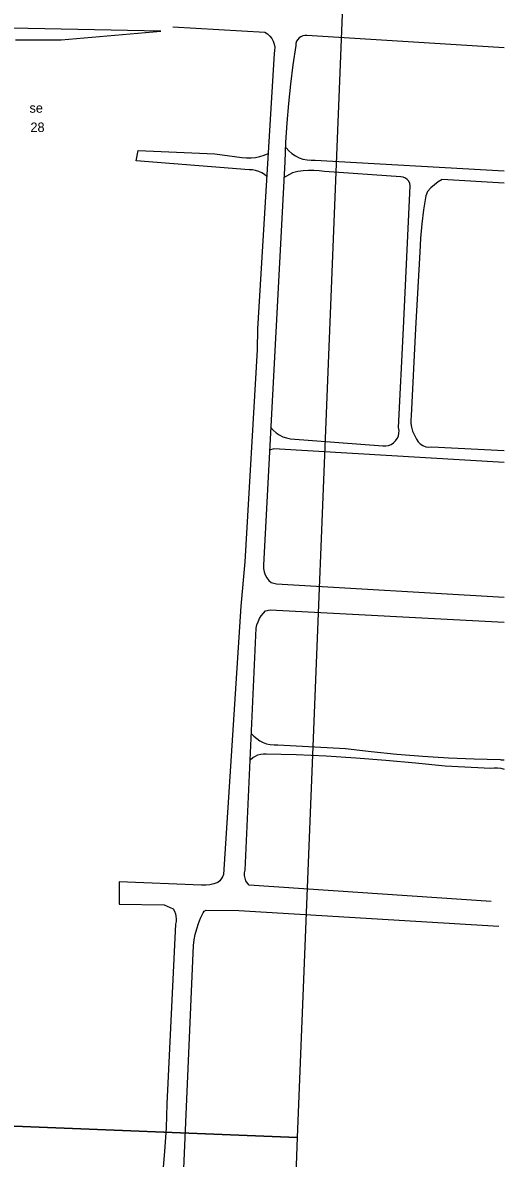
# Model space of a CAD drawing. Extents: x -9648 to 41057, y -12373 to 40276.
# Drawn here: x 9040 to 9546, y 10895 to 12090 of the extents above; entities that cross this region are included whole.
import ezdxf

# ---------------------------------------------------------------- set-up
doc = ezdxf.new("R2010")
doc.units = 0
doc.layers.add('SC_Scratch1', color=7, linetype='Continuous')
doc.layers.add('SH_Data', color=7, linetype='Continuous')

msp = doc.modelspace()

# ---------------------------------------------------------------- linework, layer by layer
at = {"layer": 'SC_Scratch1'}
for p, q in [((9419, 13174.6), (9328.4, 10916.5)), ((9328.4, 10916.5), (7789.6, 10978.2)), ((7789.6, 10978.2), (9328.4, 10916.5)), ((9328.4, 10916.5), (9237.7, 8658.3))]:
    msp.add_line(p, q, dxfattribs=at)
at = {"layer": 'SH_Data'}
for p, q in [((9184.9, 12081), (9027.9, 12084.4)), ((9197.4, 12085.7), (9294.3, 12080)), ((9079.9, 12071.9), (9184.9, 12081)), ((9294.3, 12080), (9297.1, 12078.3)), ((9297.1, 12078.3), (9299.5, 12076)), ((9299.5, 12076), (9301.6, 12073.5)), ((9301.6, 12073.5), (9303.1, 12070.6)), ((9328.9, 12072.4), (9327.8, 12070.5)), ((9330.4, 12074), (9328.9, 12072.4)), ((9332.2, 12075.3), (9330.4, 12074)), ((9334.2, 12076.2), (9332.2, 12075.3)), ((9336.4, 12076.7), (9334.2, 12076.2)), ((9338.6, 12076.6), (9336.4, 12076.7)), ((9546.3, 12063.7), (9338.6, 12076.6)), ((9032.1, 12071.9), (9079.9, 12071.9)), ((9303.1, 12070.6), (9304.2, 12067.4)), ((9304.6, 12060.9), (9304, 12057.7)), ((9304.2, 12067.4), (9304.7, 12064.2)), ((9304.7, 12064.2), (9304.6, 12060.9)), ((9326.9, 12066.1), (9323.9, 12045.8)), ((9327.1, 12068.3), (9326.9, 12066.1)), ((9327.8, 12070.5), (9327.1, 12068.3)), ((9304, 12057.7), (9286.5, 11767.9)), ((9323.9, 12045.8), (9321.3, 12025.4)), ((9321.3, 12025.4), (9319.2, 12005)), ((9319.2, 12005), (9317.4, 11984.5)), ((9317.4, 11984.5), (9316.1, 11964)), ((9158.8, 11944.5), (9161, 11955.4)), ((9161, 11955.4), (9241.8, 11951.9)), ((9316.1, 11964), (9315.2, 11943.5)), ((9316.7, 11958.4), (9319.6, 11955.2)), ((9319.6, 11955.2), (9322.9, 11952.4)), ((9277.8, 11935.1), (9158.8, 11944.5)), ((9241.8, 11951.9), (9270.1, 11948.3)), ((9270.1, 11948.3), (9275.2, 11947.7)), ((9275.2, 11947.7), (9279.9, 11947.7)), ((9279.9, 11947.7), (9284.6, 11948.1)), ((9284.6, 11948.1), (9289.2, 11949.1)), ((9289.2, 11949.1), (9293.7, 11950.6)), ((9315.2, 11943.5), (9293.1, 11519)), ((9293.7, 11950.6), (9298, 11952.5)), ((9322.9, 11952.4), (9326.5, 11950)), ((9326.5, 11950), (9330.4, 11948)), ((9330.4, 11948), (9334.4, 11946.6)), ((9334.4, 11946.6), (9338.7, 11945.6)), ((9338.7, 11945.6), (9343, 11945.2)), ((9343, 11945.2), (9347.3, 11945.4)), ((9347.3, 11945.4), (9546.3, 11934)), ((9281.3, 11935.1), (9277.8, 11935.1)), ((9284.6, 11934.6), (9281.3, 11935.1)), ((9287.9, 11933.6), (9284.6, 11934.6)), ((9291, 11932.2), (9287.9, 11933.6)), ((9293.9, 11930.4), (9291, 11932.2)), ((9296.5, 11928.3), (9293.9, 11930.4)), ((9323.4, 11932.2), (9313.9, 11926.9)), ((9328.9, 11933.3), (9323.4, 11932.2)), ((9334.5, 11934.1), (9328.9, 11933.3)), ((9340.2, 11934.4), (9334.5, 11934.1)), ((9345.8, 11934.4), (9340.2, 11934.4)), ((9351.5, 11934.1), (9345.8, 11934.4)), ((9357.1, 11933.3), (9351.5, 11934.1)), ((9437.4, 11927.9), (9357.1, 11933.3)), ((9439.9, 11927.6), (9437.4, 11927.9)), ((9442.2, 11926.6), (9439.9, 11927.6)), ((9440.4, 11768.5), (9447.3, 11918.4)), ((9444.2, 11925.1), (9442.2, 11926.6)), ((9445.8, 11923.1), (9444.2, 11925.1)), ((9446.9, 11920.9), (9445.8, 11923.1)), ((9447.3, 11918.4), (9446.9, 11920.9)), ((9472.7, 11919.4), (9468.9, 11916.1)), ((9476.7, 11922.4), (9472.7, 11919.4)), ((9481, 11925.1), (9476.7, 11922.4)), ((9546.3, 11921.2), (9481, 11925.1)), ((9463.8, 11907.8), (9461.3, 11893.1)), ((9465.4, 11912.5), (9463.8, 11907.8)), ((9468.9, 11916.1), (9465.4, 11912.5)), ((9461.3, 11893.1), (9459.4, 11878.3)), ((9459.4, 11878.3), (9458.2, 11863.4)), ((9458.2, 11863.4), (9457.5, 11848.4)), ((9457.5, 11848.4), (9452.8, 11768.3)), ((9286.5, 11767.9), (9286.3, 11745.7)), ((9434.9, 11663.9), (9440.4, 11768.5)), ((9452.8, 11768.3), (9448.4, 11676.1)), ((9286.3, 11745.7), (9273.4, 11522.6)), ((9448.4, 11676.1), (9448, 11672.1)), ((9448, 11672.1), (9448.1, 11668.1)), ((9448.1, 11668.1), (9448.7, 11664.2)), ((9300.3, 11664.3), (9303, 11661.1)), ((9303, 11661.1), (9306.1, 11658.4)), ((9306.1, 11658.4), (9309.5, 11656.1)), ((9309.5, 11656.1), (9313.2, 11654.2)), ((9313.2, 11654.2), (9317.1, 11653)), ((9433.6, 11652.3), (9434.8, 11655)), ((9434.8, 11655), (9435.4, 11658)), ((9435.5, 11661), (9434.9, 11663.9)), ((9435.4, 11658), (9435.5, 11661)), ((9448.7, 11664.2), (9449.8, 11660.3)), ((9449.8, 11660.3), (9451.3, 11656.6)), ((9451.3, 11656.6), (9453.3, 11653.1)), ((9317.1, 11653), (9321.2, 11652.2)), ((9321.2, 11652.2), (9418.5, 11644.6)), ((9418.5, 11644.6), (9421.5, 11644.6)), ((9421.5, 11644.6), (9424.4, 11645.1)), ((9424.4, 11645.1), (9427.2, 11646.2)), ((9427.2, 11646.2), (9429.7, 11647.8)), ((9429.7, 11647.8), (9431.9, 11649.8)), ((9431.9, 11649.8), (9433.6, 11652.3)), ((9453.3, 11653.1), (9453.9, 11651.7)), ((9453.9, 11651.7), (9455.6, 11649)), ((9455.6, 11649), (9457.9, 11646.7)), ((9457.9, 11646.7), (9460.6, 11645)), ((9460.6, 11645), (9463.6, 11643.8)), ((9463.6, 11643.8), (9466.7, 11643.3)), ((9466.7, 11643.3), (9469.9, 11643.5)), ((9469.9, 11643.5), (9546.3, 11639.8)), ((9303.9, 11641.6), (9299.1, 11640.1)), ((9546.3, 11627.3), (9303.9, 11641.6)), ((9273.4, 11522.6), (9269, 11476)), ((9293.1, 11519), (9293.1, 11515.6)), ((9293.1, 11515.6), (9293.6, 11512.1)), ((9293.6, 11512.1), (9294.7, 11508.8)), ((9294.7, 11508.8), (9296.4, 11505.8)), ((9296.4, 11505.8), (9298.5, 11503)), ((9298.5, 11503), (9301.1, 11500.7)), ((9301.1, 11500.7), (9306.6, 11499.4)), ((9306.6, 11499.4), (9546.3, 11485.5)), ((9269, 11476), (9250.9, 11193.6)), ((9287.2, 11459.6), (9288.7, 11462.8)), ((9288.7, 11462.8), (9290.6, 11465.8)), ((9290.6, 11465.8), (9292.8, 11468.6)), ((9292.8, 11468.6), (9295.2, 11471.1)), ((9295.2, 11471.1), (9300, 11472.1)), ((9300, 11472.1), (9546.3, 11459)), ((9273.6, 11198.2), (9285.2, 11452.7)), ((9285.2, 11452.7), (9286, 11456.2)), ((9286, 11456.2), (9287.2, 11459.6)), ((9280.1, 11341.9), (9282.8, 11339)), ((9282.8, 11339), (9285.8, 11336.5)), ((9285.8, 11336.5), (9289.1, 11334.3)), ((9289.1, 11334.3), (9292.6, 11332.5)), ((9292.6, 11332.5), (9296.2, 11331.2)), ((9296.2, 11331.2), (9300.1, 11330.3)), ((9284.4, 11318.2), (9287.1, 11319.4)), ((9287.1, 11319.4), (9290, 11320.2)), ((9290, 11320.2), (9292.9, 11320.6)), ((9292.9, 11320.6), (9295.9, 11320.6)), ((9295.9, 11320.6), (9327.4, 11319.7)), ((9300.1, 11330.3), (9304, 11329.9)), ((9304, 11329.9), (9307.9, 11329.9)), ((9307.9, 11329.9), (9379.3, 11326.2)), ((9327.4, 11319.7), (9358.8, 11318.3)), ((9379.3, 11326.2), (9406.3, 11323)), ((9406.3, 11323), (9433.3, 11320.3)), ((9433.3, 11320.3), (9460.4, 11318.1)), ((9278.9, 11314.1), (9281.8, 11316.6)), ((9281.8, 11316.6), (9284.4, 11318.2)), ((9358.8, 11318.3), (9390.2, 11316.3)), ((9390.2, 11316.3), (9421.6, 11314)), ((9421.6, 11314), (9452.9, 11311.1)), ((9452.9, 11311.1), (9484.2, 11307.7)), ((9460.4, 11318.1), (9487.6, 11316.3)), ((9484.2, 11307.7), (9532.2, 11305.3)), ((9487.6, 11316.3), (9514.7, 11315.1)), ((9514.7, 11315.1), (9541.9, 11314.4)), ((9541.9, 11314.4), (9543, 11314.3)), ((9543, 11314.3), (9544.1, 11314.2)), ((9544.1, 11314.2), (9545.2, 11314.2)), ((9545.2, 11314.2), (9546.3, 11314.3)), ((9532.2, 11305.3), (9535.7, 11305.8)), ((9535.7, 11305.8), (9539.3, 11305.8)), ((9539.3, 11305.8), (9542.8, 11305.4)), ((9542.8, 11305.4), (9546.3, 11304.5)), ((9248.5, 11188.9), (9246.9, 11186.8)), ((9249.8, 11191.2), (9248.5, 11188.9)), ((9250.9, 11193.6), (9249.8, 11191.2)), ((9273, 11195.4), (9273.6, 11198.2)), ((9273, 11192.5), (9273, 11195.4)), ((9273.5, 11189.7), (9273, 11192.5)), ((9274.5, 11187), (9273.5, 11189.7)), ((9227.6, 11182.2), (9140.9, 11185.6)), ((9140.9, 11185.6), (9141.2, 11162.3)), ((9232.1, 11182.2), (9227.6, 11182.2)), ((9236.5, 11182.6), (9232.1, 11182.2)), ((9240.8, 11183.5), (9236.5, 11182.6)), ((9245, 11184.9), (9240.8, 11183.5)), ((9246.9, 11186.8), (9245, 11184.9)), ((9276, 11184.5), (9274.5, 11187)), ((9277.9, 11182.3), (9276, 11184.5)), ((9532.4, 11164.9), (9277.9, 11182.3)), ((9141.2, 11162.3), (9188.3, 11161.7)), ((9188.3, 11161.7), (9198, 11157.2)), ((9198, 11157.2), (9199.3, 11154.8)), ((9199.3, 11154.8), (9200.2, 11152.2)), ((9200.2, 11152.2), (9200.8, 11149.5)), ((9226.7, 11147.6), (9229.3, 11153)), ((9229.3, 11153), (9230.4, 11155)), ((9230.4, 11155), (9232.5, 11156.1)), ((9232.5, 11156.1), (9266.8, 11155.5)), ((9266.8, 11155.5), (9540.7, 11139.2)), ((9200.5, 11141.2), (9191.1, 10952)), ((9201, 11144), (9200.5, 11141.2)), ((9200.8, 11149.5), (9201.1, 11146.7)), ((9201.1, 11146.7), (9201, 11144)), ((9222.7, 11136.3), (9224.5, 11142)), ((9224.5, 11142), (9226.7, 11147.6)), ((9220, 11124.6), (9221.1, 11130.5)), ((9221.1, 11130.5), (9222.7, 11136.3)), ((9207.6, 10852.4), (9219.1, 11118.7)), ((9219.1, 11118.7), (9220, 11124.6)), ((9191.1, 10952), (9190.4, 10927)), ((9190.4, 10927), (9188.9, 10902)), ((9188.9, 10902), (9186.8, 10877))]:
    msp.add_line(p, q, dxfattribs=at)

# ---------------------------------------------------------------- texts
at = {"layer": 'SC_Scratch1'}
for s, p in [('se', (9046.7, 11995.3)), ('28', (9047.7, 11975))]:
    msp.add_text(s, height=10, dxfattribs=at).set_placement(p)

doc.saveas('drawing.dxf')
